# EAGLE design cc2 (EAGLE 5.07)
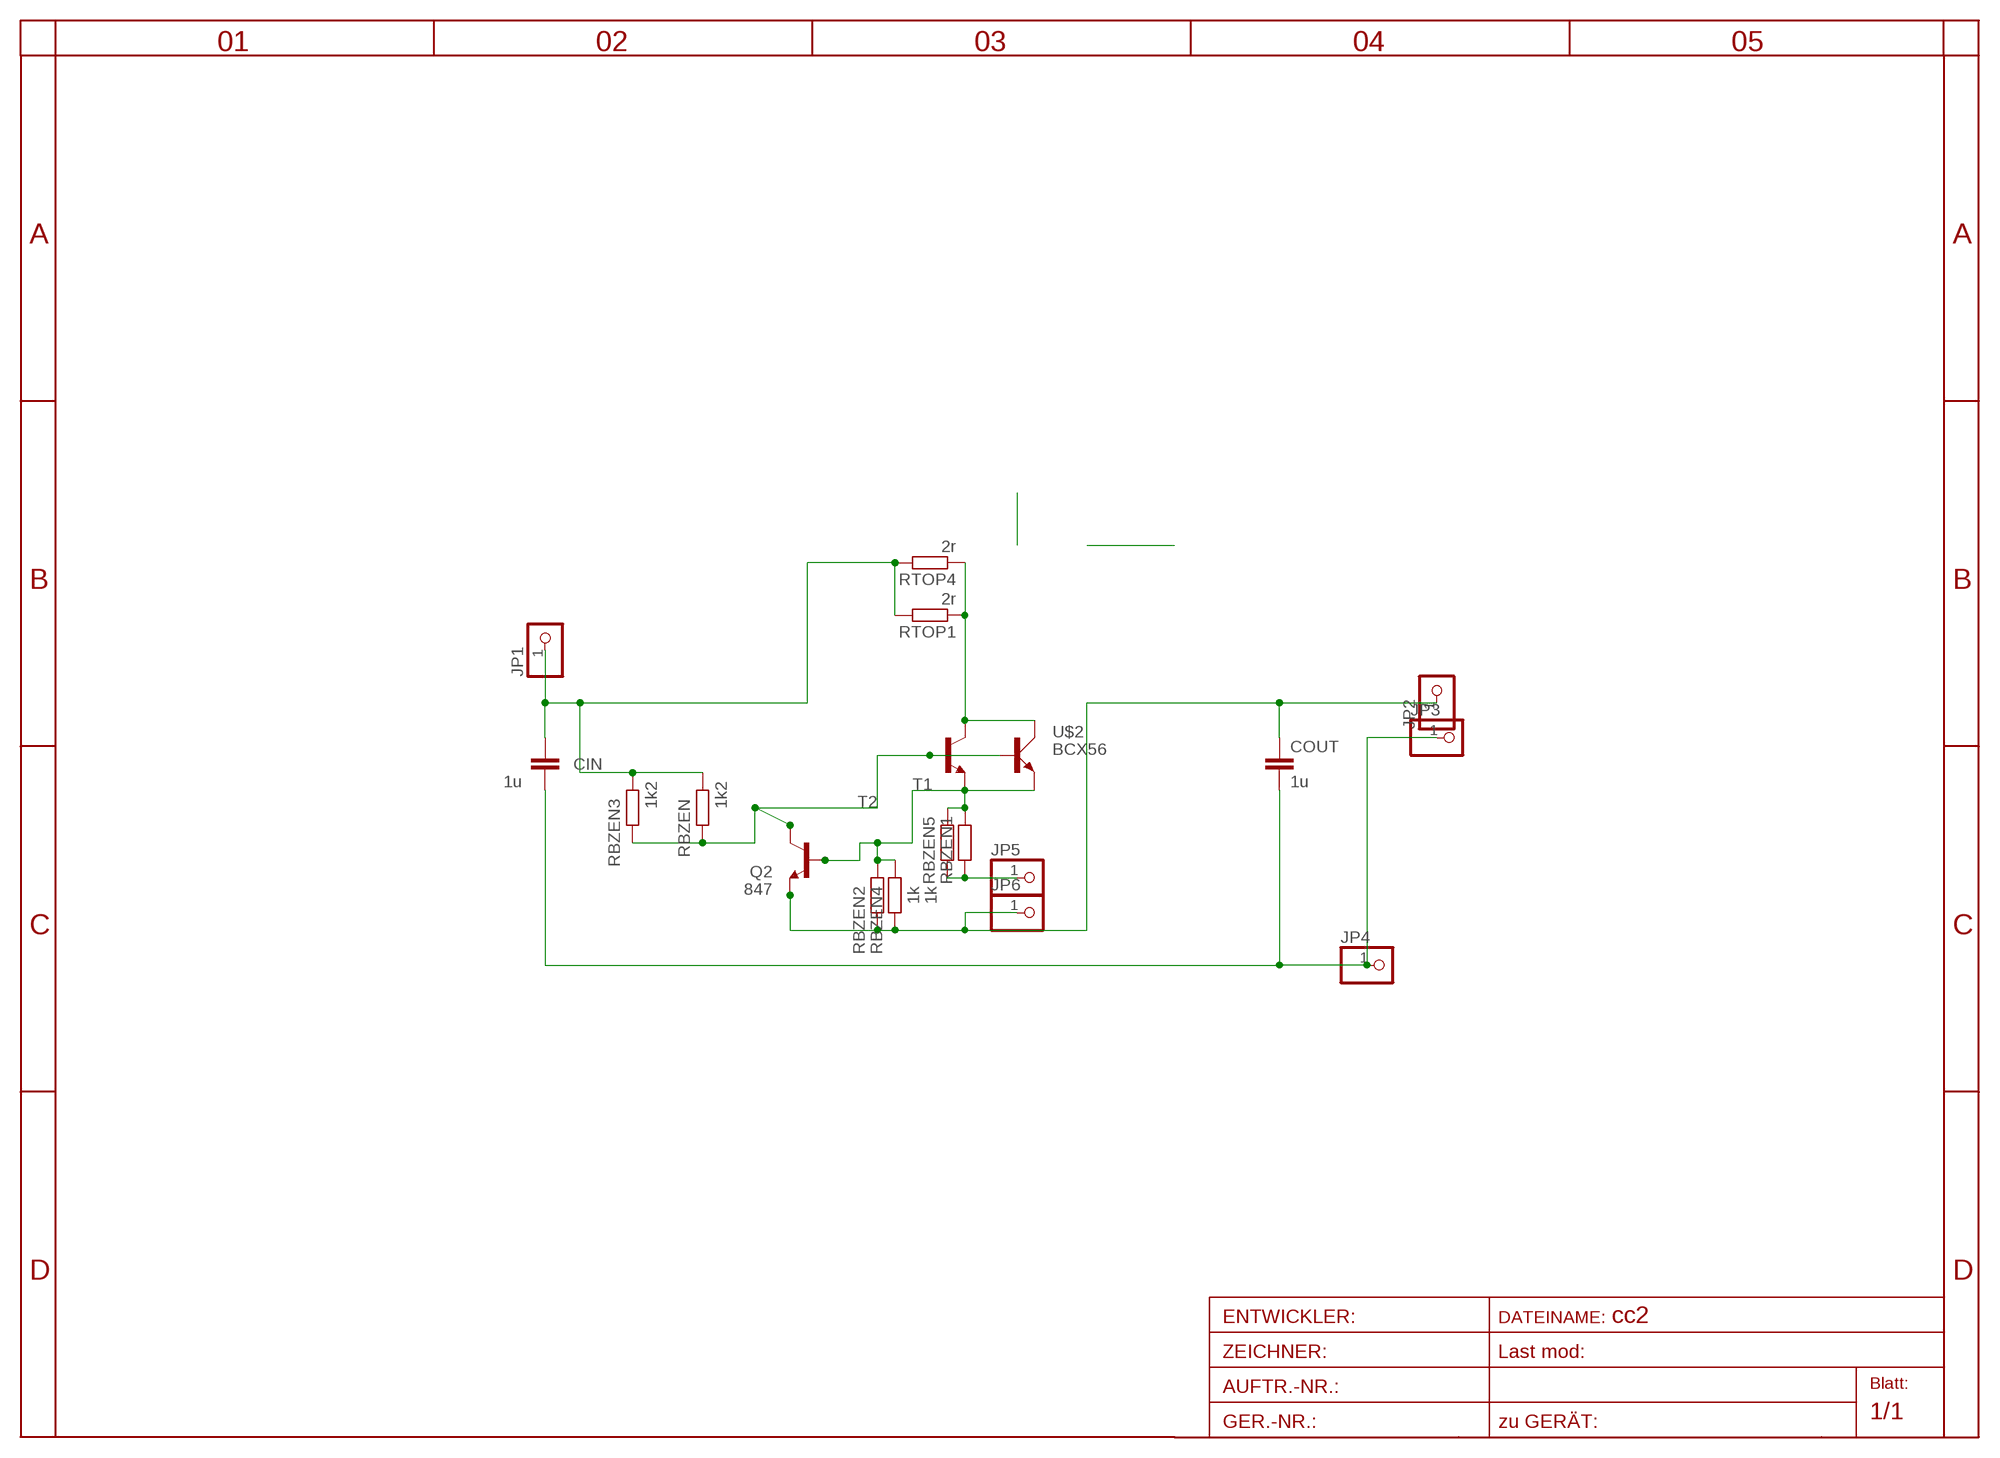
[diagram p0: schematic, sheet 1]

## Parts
CIN  1u  C-EU025-024X044  [C025-024X044]
COUT  1u  C-EU025-030X050  [C025-030X050]
JP1  PINHD-1X11X0.4  [1X01]
JP2  PINHD-1X11X0.4  [1X01]
JP3  PINHD-1X11X0.4  [1X01]
JP4  PINHD-1X11X0.4  [1X01]
JP5  PINHD-1X11X0.4  [1X01]
JP6  PINHD-1X11X0.4  [1X01]
Q2  847  BC847ASMD  [SOT23]
RBZEN  1k2  R-EU_0207/7  [0207/7]
RBZEN1  7r2  R-EU_0204/7  [0204/7]
RBZEN2  1k  R-EU_0204/7  [0204/7]
RBZEN3  1k2  R-EU_R1206  [R1206]
RBZEN4  1k  R-EU_R1206  [R1206]
RBZEN5  7r2  R-EU_R1206  [R1206]
RTOP1  2r  R-EU_M1206  [M1206]
RTOP4  2r  R-EU_0204/7  [0204/7]
T1  -NPN-TO126V  [TO126V]
T2  BC337-40-NPN-TO92-EBC  [TO92-EBC]
U$2  BCX56  [SOT223]

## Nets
C: RTOP1.1 RTOP4.1 T1.2(C) U$2.2(C)
CB: Q2.3(C) RBZEN3.2 RBZEN.2 T1.3(B) T2.C U$2.1(B)
EB: Q2.1(B) RBZEN1.1 RBZEN2.1 RBZEN4.1 RBZEN5.1 T1.1(E) T2.B U$2.3(E)
GND: CIN.2 COUT.2 JP3.1 JP4.1
OUT: COUT.1 JP2.1 JP6.1 Q2.2(E) RBZEN2.2 RBZEN4.2 T2.E
SWTCH: JP5.1 RBZEN1.2 RBZEN5.2
VPLUS: CIN.1 JP1.1 RBZEN3.1 RBZEN.1 RTOP1.2 RTOP4.2

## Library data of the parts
CIN COUT = rcl:C-EU: CAPACITOR, European symbol
JP1-JP6 = pinhead:PINHD-1X1: PIN HEADER
Q2 = transistor-npn:BC847*: NPN Transistor
RBZEN RBZEN1-RBZEN5 RTOP1 RTOP4 = rcl:R-EU_: RESISTOR, European symbol
T1 T2 = transistor:*-NPN-: NPN Transistror BF959 corrected 2008.03.06
U$2 = transistor-power:BCX56

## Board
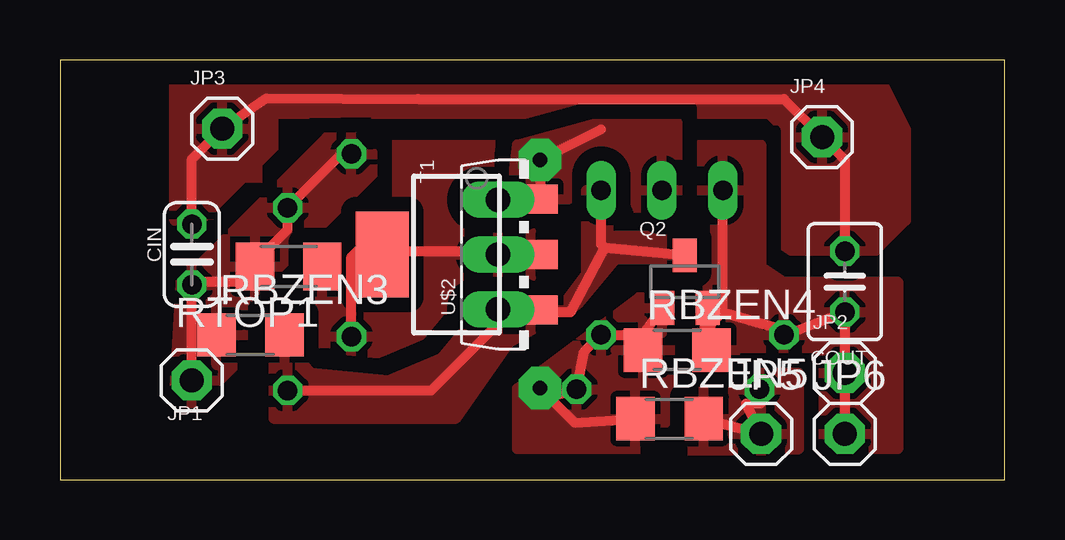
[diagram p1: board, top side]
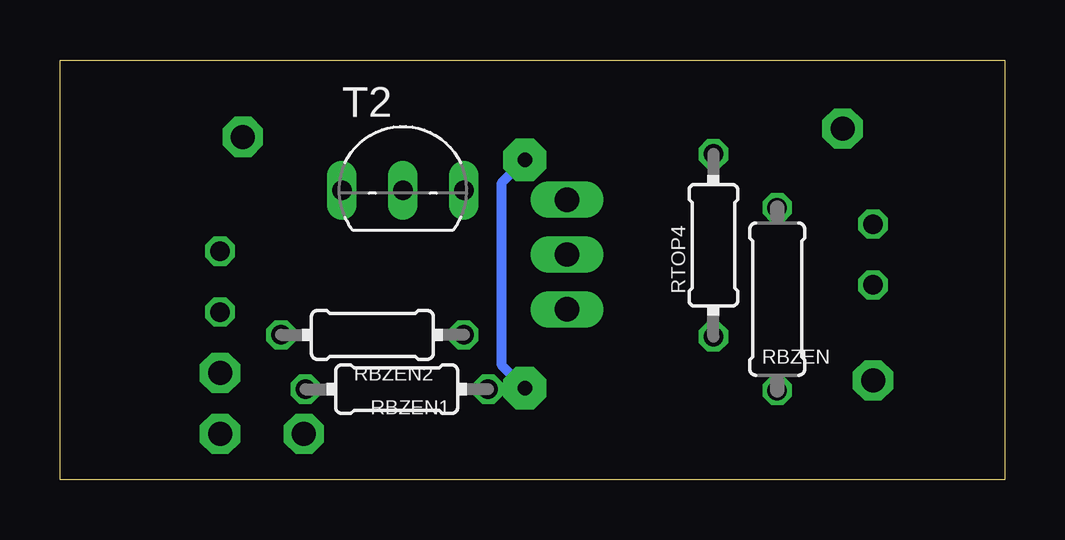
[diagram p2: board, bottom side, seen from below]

Size 39.37 x 17.5 mm. Coordinates in mm from the lower left corner, seen from the top.
Outline: 0,0 39.37,0 39.37,17.5 0,17.5 0,0
Copper layers (1*16): Top 0.035mm / dielectric 1.5mm / Bottom 0.035mm
Design rules "default *": minimum track width 10mil, minimum drill 20mil, track to track 8mil, track to pad 8mil, pad to pad 8mil, via to via 8mil, smd to smd 8mil, copper to edge 40mil, drill to drill 8mil, minimum pad ring 1mil, minimum via ring 8mil, stop-mask expansion 4mil, vias tented up to drill 0mil, thermal gap 10mil

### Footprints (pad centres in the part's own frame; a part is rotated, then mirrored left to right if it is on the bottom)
C025-024X044 = drill 0.813 octagon: 1 -1.27,0; 2 1.27,0
C025-030X050 = drill 0.813 octagon: 1 -1.27,0; 2 1.27,0
1X01 = drill 1 pad 1.676 octagon: 1 0,0
SOT23 = smd 1 x 1.4: 1 -0.95,-1.1; 2 0.95,-1.1; 3 0,1.1
0207/7 = drill 0.813 octagon: 1 -3.81,0; 2 3.81,0
0204/7 = drill 0.813 octagon: 1 -3.81,0; 2 3.81,0
R1206 = smd 1.6 x 1.803: 1 -1.422,0; 2 1.422,0
M1206 = smd 1.6 x 2: 1 -1.4,0; 2 1.4,0
TO126V = drill 1.016 long: 1 -2.286,-1.27; 2 0,-1.27; 3 2.286,-1.27
TO92-EBC = drill 0.813 long: B 0,-1.27; C 2.54,-1.27; E -2.54,-1.27
SOT223 = smd 1.219 x 2.235: 1 -2.311,-3.099; 2 0,-3.099; 3 2.311,-3.099 | smd 3.6 x 2.2: 4 0,3.099

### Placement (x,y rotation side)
CIN  5.49,9.38 90 top
COUT  32.7,8.26 90 top
JP1  5.49,4.13 0 top
JP2  32.7,4.45 0 top
JP3  6.76,14.63 0 top
JP4  31.75,14.29 0 top
JP5  29.21,1.91 0 top
JP6  32.7,1.91 0 top
Q2  26.04,8.26 0 top
RBZEN  9.48,7.53 270 bottom
RBZEN1  25.34,3.77 180 bottom
RBZEN2  26.35,6.03 180 bottom
RBZEN3  7.94,6.03 0 top
RBZEN4  25.72,5.4 0 top
RBZEN5  25.4,2.54 0 top
RTOP1  9.53,8.89 180 top
RTOP4  12.14,9.77 90 bottom
T1  19.52,9.38 270 top
T2  25.08,13.34 0 bottom
U$2  16.52,9.38 90 top

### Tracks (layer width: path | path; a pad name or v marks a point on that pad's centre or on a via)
C
  Top 0.406: RTOP4.1 12.14,9.29 12.38,9.53 18.11,9.53 T1.2 U$2.2
  pour Top (isolate 0.61, rank 4): 11.43,13.97 20.32,13.97 20.32,6.35 13.97,5.08 10.16,5.08
CB
  Top 0.406: 22.69,9.67 Q2.3 | 22.69,9.67 21.27,6.99 18.73,6.99 | 18.73,6.99 18.37,6.99 T1.3 | T2.C 22.54,9.82 22.69,9.67 | RBZEN.2 15.46,3.72 18.73,6.99 | U$2.1 18.82,7.07 18.73,6.99
  pour Top (isolate 0.61): 8.89,6.35 8.89,2.54 16.51,2.54 18.73,5.71 21.59,7.3 23.18,9.21 25.4,9.21 25.4,10.16 22.86,10.16 22.86,12.38 21.91,12.06 21.91,8.57 20.95,7.3 17.46,6.99 15.88,5.08 13.65,4.13 10.48,4.45
EB  (via drill 0.6 pad 1.78)
  Top 0.406: 22.54,14.61 v20,13.34 20,12.08 U$2.3 18.28,11.7 T1.1 | 20.36,3.45 RBZEN1.1 21.85,5.34 RBZEN2.1 23.81,6.03 | v20,3.81 20.36,3.45 | 23.81,6.03 24.28,6.03 Q2.1 | RBZEN4.1 24.3,5.55 23.81,6.03 | RBZEN5.1 21.44,2.37 20.36,3.45
  Bottom 0.406: v20,13.34 20.95,12.38 20.95,4.76 v20,3.81
  pour Top (isolate 0.61, rank 2): 24.13,7.62 25.4,7.62 25.4,2.54 24.13,1.27 19.05,1.27 19.05,3.81
  pour Top (isolate 0.61): 19.05,13.97 22.54,14.92 25.72,14.92 25.72,11.11 24.13,11.11 23.5,12.7 20.64,11.43 18.73,11.43
GND
  Top 0.406: CIN.2 5.49,13.37 JP3.1 8.6,15.9 14.92,15.88 30.16,15.88 JP4.1 32.7,13.34 COUT.2
  pour Top (isolate 0.61, rank 3): 4.76,10.79 4.76,17.14 33.97,17.14 35.24,14.61 35.24,10.79 33.97,9.53 30.16,9.53 30.16,14.61 29.53,15.24 8.89,15.24 8.89,11.43 8.26,10.79
OUT
  Top 0.406: 26.99,6.35 26.84,6.2 Q2.2 30.33,6.2 | 26.99,6.35 27.62,6.99 T2.E | 30.33,6.2 30.65,6.2 COUT.1 JP2.1 JP6.1 | 30.33,6.2 RBZEN2.2 | RBZEN4.2 27.14,6.2 26.99,6.35
  pour Top (isolate 0.61, rank 2): 26.67,13.97 29.21,13.97 29.21,8.89 30.16,8.26 34.92,8.26 34.92,1.27 31.75,1.27 31.75,5.08 26.67,5.08 26.67,7.62
SWTCH
  Top 0.406: RBZEN1.2 29.19,3.17 28.57,3.17 JP5.1 RBZEN5.2
  pour Top (isolate 0.61): 30.48,1.27 30.8,1.27 30.8,4.45 26.35,4.45 26.35,0.95
VPLUS
  Top 0.406: JP1.1 CIN.1 5.63,8.26 7.3,8.26 9.48,10.44 RBZEN.1 11.73,13.58 RTOP4.2
  pour Top (isolate 0.61, rank 2): 5.08,8.89 5.71,8.89 11.11,14.29 12.38,14.29 13.02,13.65 13.02,12.7 8.89,8.57 7.62,7.3 7.62,5.08 5.71,3.17 5.08,3.17 4.76,3.49

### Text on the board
tStop: MICHAEL5.net
bStop: MICHAEL5.net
